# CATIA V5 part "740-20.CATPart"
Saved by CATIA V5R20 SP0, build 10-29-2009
Part number: 740-20
Bounding box of the stored display mesh (mm): x -19.9 to 19.9, y -18 to 19.9, z -23 to 12
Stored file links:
  C:\Users\Utente\Desktop\IO LAVORO\3D X SITO CF\X SITO\740\740-20.CATPart
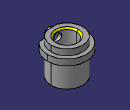
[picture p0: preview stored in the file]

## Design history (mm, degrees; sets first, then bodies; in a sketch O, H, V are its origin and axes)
Set1
  DatumSurface1 to DatumSurface35 "740-20"
Body1 (main body)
